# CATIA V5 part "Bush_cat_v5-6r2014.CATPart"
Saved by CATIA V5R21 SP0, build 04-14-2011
Part number: Bush
Bounding box of the stored display mesh (mm): x 75 to 115, y 10 to 50, z 160 to 210
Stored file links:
  D:\APS\CATIA V5-6R-2013-Project\CATIA V5-6R2013_partfiles\Tutorials\c12_catia_v5-6r2013_tut\c12tut2\Bush_cat_v5-6r2013.CATPart
  D:\APS\CATIA V5-6R-2013-Project\CATIA V5-6R2013_partfiles\Tutorials\c12_catia_v5-6r2013_tut\c12tut2\Assembly_cat_v5-6r2013.CATProduct
  D:\CATIA V5R21 E-RESOURCES\CATIA-V5R21\catia-v5r21-Tut\c12-catia-v5r21-tut\c12-catia-v5r21-tut02\Guide Pillar.CATPart
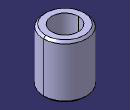
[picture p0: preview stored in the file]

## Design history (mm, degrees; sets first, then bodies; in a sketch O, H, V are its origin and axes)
Set1
  DatumSurface1: linked copy from another document
  DatumCurve1: linked copy from another document
Body1 (main body)
  Sketch1 on face of DatumSurface1, origin (0, 0, 200), H (1, 0, 0), V (0, 1, 0)
    projected circle E1 centre (95, 30) radius 12.5 from edge of DatumCurve1
    circle A1 centre (95, 30) radius 20
    point P1 (95, 30)
    radius A1 = 20
    concentricity: P1 E1, A1 E1
  Pad1: profile Sketch1, direction (0, 0, 1), length 10, opposite side length 40
  Chamfer1: length 2, angle 45, on face of Pad1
